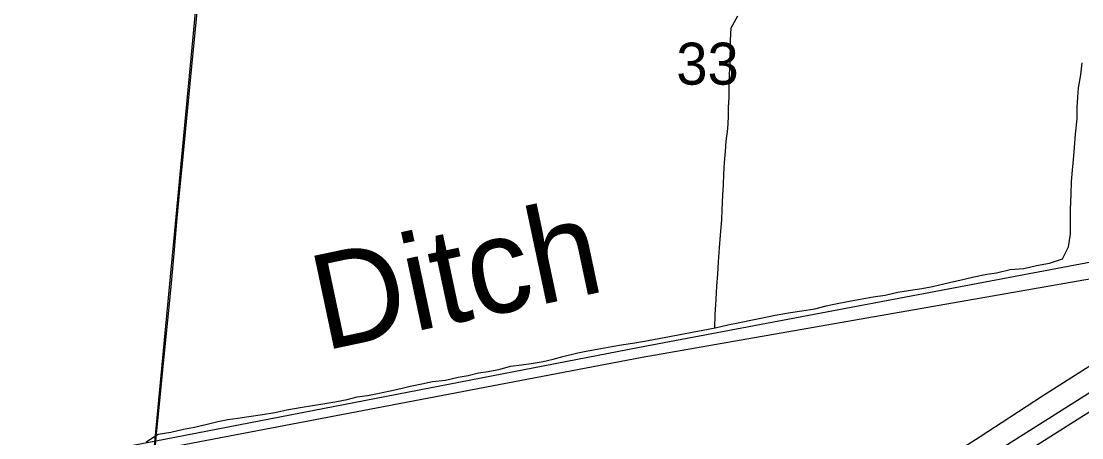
# Model space of a CAD drawing. Extents: x 0 to 34, y 0 to 22.
# Drawn here: x 2.851 to 3.909, y 16.564 to 16.978 of the extents above; entities that cross this region are included whole.
import ezdxf

# ---------------------------------------------------------------- set-up
doc = ezdxf.new("R2010")
doc.units = 0
for name, color, linetype in [('Default', 7, 'Continuous'), ('GM_X_County_Road', 7, 'Continuous'), ('GM_X_Minor_River', 7, 'Continuous'), ('GM_X_Minor_River_Text', 7, 'Continuous'), ('GM_X_Rail_Line', 7, 'Continuous'), ('GM_X_Section', 7, 'Continuous'), ('GM_X_Section_Text', 7, 'Continuous'), ('GM_X_State_Route', 7, 'Continuous')]:
    doc.layers.add(name, color=color, linetype=linetype)

msp = doc.modelspace()

# ---------------------------------------------------------------- linework, layer by layer
at = {"layer": 'Default'}
msp.add_lwpolyline([(2.1, 17.5957), (2.1, 16.5883), (2.9781, 16.4922), (3.0746, 17.5112)], close=True, dxfattribs=at)
at = {"layer": 'GM_X_County_Road'}
for points in [[(2.9784, 16.4925), (2.9812, 16.5165), (2.9843, 16.5443), (2.986, 16.5637), (2.9887, 16.5938), (2.9925, 16.6309), (2.9963, 16.6679), (2.9989, 16.6938), (3.0013, 16.7176), (3.0037, 16.7471), (3.0066, 16.7788), (3.0088, 16.8036), (3.0127, 16.8437), (3.0215, 16.9333), (3.0314, 17.0353), (3.0418, 17.1403), (3.0465, 17.1867), (3.0502, 17.2237), (3.0525, 17.2485), (3.0578, 17.3041), (3.0629, 17.3567), (3.0639, 17.3666)], [(3.7443, 16.5246), (3.8072, 16.5647), (3.8368, 16.5841), (3.8693, 16.6054), (3.9296, 16.6436)]]:
    msp.add_lwpolyline(points, dxfattribs=at)
at = {"layer": 'GM_X_Minor_River'}
for points in [[(3.5426, 16.673), (3.5432, 16.6864), (3.5441, 16.7012), (3.5447, 16.7149), (3.5456, 16.7262), (3.5465, 16.7388), (3.5474, 16.7528), (3.5483, 16.7653), (3.5497, 16.7805), (3.5502, 16.7907), (3.5507, 16.8056), (3.5512, 16.8154), (3.5517, 16.826), (3.5523, 16.8378), (3.5535, 16.8488), (3.5541, 16.8591), (3.5557, 16.8712), (3.5562, 16.883), (3.5564, 16.8924), (3.5569, 16.9027), (3.557, 16.9164), (3.5575, 16.9258), (3.558, 16.9357), (3.5583, 16.9593), (3.5589, 16.9718), (3.5655, 16.9839)], [(3.4162, 16.65), (3.4292, 16.6525), (3.4402, 16.6546), (3.4516, 16.6564), (3.4631, 16.6581), (3.4764, 16.6603), (3.487, 16.6624), (3.5099, 16.6667), (3.5202, 16.6688), (3.5308, 16.6706), (3.543, 16.6731), (3.5556, 16.676), (3.5659, 16.6782), (3.5769, 16.6803), (3.5887, 16.6828), (3.6028, 16.6857), (3.618, 16.6885), (3.6295, 16.6899), (3.6424, 16.692), (3.6538, 16.6949), (3.6664, 16.6978), (3.6786, 16.7), (3.6896, 16.7021), (3.7007, 16.7039), (3.7125, 16.7056), (3.725, 16.7085), (3.7357, 16.7103), (3.749, 16.7124), (3.7597, 16.7142), (3.7768, 16.7182), (3.7913, 16.7214), (3.8008, 16.7239), (3.8138, 16.7264), (3.8236, 16.7278), (3.837, 16.7311), (3.8507, 16.7321), (3.8632, 16.735), (3.8762, 16.7375), (3.8892, 16.7419), (3.8954, 16.7536), (3.8974, 16.7665), (3.8972, 16.7805), (3.8974, 16.7911), (3.8979, 16.8063), (3.8981, 16.8188), (3.8994, 16.8302), (3.9002, 16.8405), (3.9012, 16.8526), (3.9021, 16.8659), (3.9038, 16.8811), (3.9039, 16.8928), (3.9044, 16.9027), (3.9053, 16.9122), (3.9074, 16.9251), (3.909, 16.9372)], [(2.976, 16.5596), (2.9879, 16.5671), (3.0004, 16.5692), (3.013, 16.5721), (3.024, 16.5742), (3.0366, 16.5771), (3.0473, 16.5797), (3.0572, 16.5818), (3.0671, 16.5832), (3.0781, 16.5846), (3.0918, 16.5867), (3.104, 16.5888), (3.1162, 16.5913), (3.1295, 16.5938), (3.1417, 16.5956), (3.1539, 16.5977), (3.1641, 16.5995), (3.1763, 16.6016), (3.1862, 16.6042), (3.1965, 16.6056), (3.2064, 16.6077), (3.219, 16.6102), (3.2296, 16.6127), (3.2392, 16.6149), (3.2506, 16.6174), (3.2613, 16.6196), (3.2742, 16.6209), (3.2868, 16.6238), (3.2967, 16.6256), (3.3073, 16.6281), (3.3168, 16.6295), (3.3286, 16.632), (3.3389, 16.635), (3.35, 16.6363), (3.3595, 16.6377), (3.3717, 16.6395), (3.3816, 16.642), (3.3911, 16.6446), (3.4063, 16.6482), (3.4162, 16.65)]]:
    msp.add_lwpolyline(points, dxfattribs=at)
at = {"layer": 'GM_X_Rail_Line'}
for points in [[(4.0546, 16.7612), (3.9616, 16.7467), (3.4677, 16.6534), (2.9837, 16.5597), (2.5251, 16.4729), (2.1965, 16.4061), (2.1, 16.3871)], [(2.1, 16.3819), (2.1525, 16.3929), (3.4702, 16.644), (4.0569, 16.7466), (4.1104, 16.7574)]]:
    msp.add_lwpolyline(points, dxfattribs=at)
at = {"layer": 'GM_X_Section'}
msp.add_lwpolyline([(3.0746, 17.5112), (4.0957, 17.4007), (4.0036, 16.3979), (2.9781, 16.4922)], close=True, dxfattribs=at)
at = {"layer": 'GM_X_State_Route'}
for points in [[(3.0798, 16.0631), (3.0902, 16.0698), (3.1749, 16.123), (3.251, 16.1708), (3.3377, 16.2246), (3.4148, 16.2731), (3.5025, 16.3285), (3.5918, 16.3847), (3.6821, 16.4418), (3.7438, 16.4804), (3.826, 16.5327), (3.9164, 16.5896), (4.0141, 16.6512), (4.1043, 16.7081), (4.1994, 16.7678), (4.2857, 16.8225), (4.3394, 16.8561)], [(2.7904, 15.8714), (2.8213, 15.8985), (2.844, 15.9174), (2.8687, 15.9371), (2.8859, 15.9503), (2.9071, 15.9662), (2.9197, 15.9753), (2.9264, 15.9804), (2.9395, 15.9903), (2.9573, 16.0028), (2.9935, 16.0269), (3.0353, 16.0537), (3.1032, 16.0964), (3.2403, 16.1828), (3.3605, 16.2577), (3.5006, 16.3467), (3.5479, 16.3765), (3.6635, 16.4494), (3.8502, 16.5669), (3.908, 16.6033), (3.9632, 16.6381)]]:
    msp.add_lwpolyline(points, dxfattribs=at)

# ---------------------------------------------------------------- texts
at = {"layer": 'GM_X_Minor_River_Text'}
msp.add_text('Ditch', height=0.09469, rotation=11.9823, dxfattribs=at).set_placement((3.153, 16.6501))
at = {"layer": 'GM_X_Section_Text'}
msp.add_text('33', height=0.04186, rotation=0, dxfattribs=at).set_placement((3.5043, 16.9153))

doc.saveas('drawing.dxf')
